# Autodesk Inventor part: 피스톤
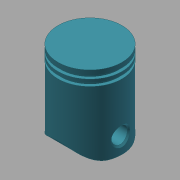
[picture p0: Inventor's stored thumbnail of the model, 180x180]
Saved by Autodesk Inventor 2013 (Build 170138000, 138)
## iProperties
Created: 2017-05
Part Number: 피스톤
Material: 일반
Document SubType Name: Modeling
Designer: mduedu
Density: 2.71 g/cm^3
Mass: 87.6982 g
Surface Area: 150.47 cm^2
Volume: 32.361 cm^3
Author: mduedu
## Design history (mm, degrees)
sketch "스케치1"
  geometry: L1 (0, 0)-(20, 0); L2 (20, -50)-(15, -50); L3 (15, -50)-(15, -5); L4 (15, -5)-(0, -5); L5 (0, -5)-(0, 0); L6 (20, -3)-(18, -3); L7 (18, -3)-(18, -5); L8 (18, -5)-(20, -5); L9 (20, -7)-(18, -7); L10 (18, -7)-(18, -9); L11 (18, -9)-(20, -9); L12 (20, 0)-(20, -3); L13 (20, -5)-(20, -7); L14 (20, -9)-(20, -50); L15 (0, -60)-(0, 10) reference
  constraints: 28 end point, 10 parallel, 5 perpendicular, 4 collinear, 3 horizontal
  dimensions: "d0" = 20 distance of L1.start L1.end; "d1" = 2 distance of L6.start L6.end; "d2" = 2 distance of L6.end L7.end; "d3" = 2 distance of L8.end L9.start; "d4" = 3 distance of L1.end L6.start; "d5" = 5 distance of L2.start L2.end; "d6" = 50 distance between parallel lines of L1 L2; "d7" = 5 distance of L4.end L1.start
revolve "회전1" sketch "스케치1" stored, may be unused: angle "d8" = 90 deg
fillet "모깎기1" dims "d9" = 1
sketch "스케치2"
  geometry: L1 (-50, 15)-(-50, -15) reference; C1 r 10 at (-40, 0); 1 further point
  constraints: 1 centre point, 1 horizontal alignment
  dimensions: "d10" = 20 diameter of C1; "d11" = 10 distance from line of C1.centre L1
extrude "돌출1" join sketch "스케치2" stored distance "d12" = 10; taper "d13" = 0 deg
sketch "스케치3"
  geometry: L1 (0, -20)-(-3, -20) reference; L2 (-3, -20)-(-3, -18) reference; L3 (-3, -18)-(-5, -18) reference; L4 (-5, -18)-(-5, -20) reference; L5 (-5, -20)-(-7, -20) reference; L6 (-7, -20)-(-7, -18) reference; L7 (-7, -18)-(-9, -18) reference; L8 (-9, -18)-(-9, -20) reference; L9 (-9, -20)-(-50, -20) reference; L10 (-50, -20)-(-50, -15) reference; L11 (-50, -15)-(-6, -15) reference; L12 (-5, -14)-(-5, 14) reference; L13 (-6, 15)-(-50, 15) reference; L14 (-50, 15)-(-50, 20) reference; L15 (-50, 20)-(-9, 20) reference; L16 (-9, 20)-(-9, 18) reference; L17 (-9, 18)-(-7, 18) reference; L18 (-7, 18)-(-7, 20) reference; L19 (-7, 20)-(-5, 20) reference; L20 (-5, 20)-(-5, 18) reference; L21 (-5, 18)-(-3, 18) reference; L22 (-3, 18)-(-3, 20) reference; L23 (-3, 20)-(0, 20) reference; L24 (0, 20)-(0, -20) reference; C1 r 10 at (-40, 0) reference; C2 r 5 at (-40, 0); A1 r 1 centre (-6, -14) between (-6, -15) and (-5, -14) reference; A2 r 1 centre (-6, 14) between (-5, 14) and (-6, 15) reference; 1 further point
  constraints: 1 centre point, 1 coincident
  dimensions: "d15" = 10 diameter of C2
extrude "돌출2" cut sketch "스케치3" stored distance "d16" = 10; taper "d17" = 0 deg
sketch "스케치4"
  geometry: L1 (15, -50)-(-15, -50) reference; L2 (-15, -50)-(-20, -50) reference; L3 (-20, -50)-(-20, -45) reference; L4 (20, -45)-(20, -50) reference; L5 (20, -50)-(15, -50) reference; L6 (-15, -30)-(15, -30) reference; L7 (15, -30)-(15, -6) reference; L8 (14, -5)-(-14, -5) reference; L9 (-15, -6)-(-15, -30) reference; L10 (-20, -3)-(-20, 0) reference; L11 (-20, 0)-(20, 0) reference; L12 (20, 0)-(20, -3) reference; L13 (20, -3)-(18, -3) reference; L14 (18, -3)-(18, -5) reference; L15 (18, -5)-(20, -5) reference; L16 (20, -5)-(20, -7) reference; L17 (20, -7)-(18, -7) reference; L18 (18, -7)-(18, -9) reference; L19 (18, -9)-(20, -9) reference; L20 (-20, -9)-(-18, -9) reference; L21 (-18, -9)-(-18, -7) reference; L22 (-18, -7)-(-20, -7) reference; L23 (-20, -7)-(-20, -5) reference; L24 (-20, -5)-(-18, -5) reference; L25 (-18, -5)-(-18, -3) reference; L26 (-18, -3)-(-20, -3) reference; L27 (0, 0)-(0, -50); L28 (-5.698, -50)-(-5, -30); L29 (5.698, -50)-(5, -30); L30 (-5, -30)-(5, -30); L31 (-5.698, -50)-(5.698, -50); L32 (-20, -45)-(20, -45) reference; L33 (20, -9)-(20, -35) reference; L34 (20, -35)-(-20, -35) reference; L35 (-20, -35)-(-20, -9) reference; A1 r 1 centre (14, -6) between (15, -6) and (14, -5) reference; A2 r 1 centre (-14, -6) between (-14, -5) and (-15, -6) reference
  constraints: 10 end point, 2 point on line, 2 symmetric about line, 1 midpoint, 1 parallel, 1 perpendicular
  dimensions: "d18" = 2 deg angle of L27 L28; "d19" = 5 distance from line of L27 L28.end
extrude "돌출3" cut sketch "스케치4" stored distance "d20" = 20; taper "d21" = 0 deg
chamfer "모따기1" distance "d22" = 1; stored, may be unused: second distance "d23" = 2, angle "d24" = 45 deg
sketch "스케치5"
  geometry: L1 (-50, 0)-(-50, -15) reference; L2 (-50, 15)-(-50, 0) reference; L3 (-9, 20)-(-50, 20) reference; L4 (-50, 20)-(-50, -20) reference; L5 (-9, -20)-(-50, -20) reference; L6 (-42.483, -20)-(-50, -20); L7 (-50, -20)-(-50, -7); L8 (-42.483, 20)-(-50, 20); L9 (-50, 20)-(-50, 7); A1 r 15 centre (-35, 7) between (-42.483, 20) and (-50, 7); A2 r 15 centre (-35, -7) between (-42.483, -20) and (-50, -7); 1 further point
  constraints: 8 end point, 4 point on circle, 4 point on line, 2 centre point, 2 tangent, 1 collinear, 1 equal radius, 1 perpendicular
  dimensions: "d25" = 30 diameter of A1; "d26" = 7 vertical distance of A2.centre point (0, 0); "d27" = 7 vertical distance of point (0, 0) A1.centre (= d26)
extrude "돌출4" cut sketch "스케치5" stored distance "d28" = 20; taper "d29" = 0 deg
node "솔리드1"
node "절단 모서리 투영1"
node "절단 모서리 투영2"
